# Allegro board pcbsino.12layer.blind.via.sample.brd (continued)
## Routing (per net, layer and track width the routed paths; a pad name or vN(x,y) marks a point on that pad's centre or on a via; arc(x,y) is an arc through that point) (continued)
VDD_GPU: length 26.6
  TOP w0.114: L6.2 18.88,64.43 ; TP13.1 16.45,63.67 16.65,63.87 v7(16.76,63.87) ; 17.72,63.51 v7(17.59,63.39)
  TOP w0.254: v8(33.47,31.97) U6.W11 v8(33.47,32.77) U6.W10 ; v8(33.47,31.97) U6.W10 ; v8(33.47,31.97) U6.V11 ; v8(33.47,31.97) U6.V10 ; U6.W10 v8(34.27,31.97) U6.V10 ; v8(33.47,31.17) U6.U11 v8(32.67,31.17) ; v8(33.47,31.17) U6.V11 ; v8(33.47,31.17) U6.V10 ; U6.V14 v8(31.07,31.97) U6.W13 ; U6.V11 v8(32.67,31.17) ; v8(32.67,31.17) U6.U12
  INT_L3 w0.254: 27.5,57.37 28.01,57.37 28.34,57.04 28.34,56.99 28.44,56.89 28.44,56.32 v2(28.34,56.22)
  INT_L3 w0.381: 27.5,57.37 27.07,56.93 25.98,56.93 25.52,57.39 24.78,57.39 18.79,63.39 v7(17.59,63.39)
  SIG_L10 w0.091: v3(30.5,47.1) 30.5,47.43 v5(30.55,47.49)
  BOTTOM w0.254: 33.16,31.57 33.16,31.49 v8(33.47,31.17) ; v8(31.07,31.97) 30.99,31.89 C247.1
  vias: v7(16.78,64.43) v7(17.37,64.43) v7(17.34,63.89)
VDD_IVA: length 25.7
  TOP w0.114: L8.2 17.95,51.85 TP18.1 v7(16.88,54.34)
  TOP w0.254: U6.V18 v8(27.07,31.17) ; v8(27.07,31.17) U6.V19 v8(26.27,31.17) U6.U19 v8(27.07,31.17) ; v8(27.07,31.17) U6.U18 ; U3.L11 v7(27.93,52.62)
  INT_L3 w0.381: v7(16.88,54.34) 16.96,54.42 23.31,54.42 24.2,53.53 27.02,53.53 v7(27.93,52.62)
  SIG_L10 w0.091: v5(26.31,46.06) 26,46.06 v3(25.72,46.34)
  BOTTOM w0.114: C39.1 17.05,52.83 C244.1 16.88,53.4 v7(16.88,54.34) ; v7(27.93,52.62) 28.63,51.92 C241.1
  vias: v4(25.26,46.93) v5(25.26,46.93) v7(16.5,54.75) v7(16.91,55.05) v7(17.42,54.99)
VDD_MPU: length 47.9
  TOP w0.254: U6.M18 v8(27.07,27.17) U6.N18 ; U6.M18 v8(27.87,26.37) ; U6.M18 v8(27.87,27.17) ; U6.M18 v8(27.07,26.37) ; U6.L18 v8(27.07,26.37) ; U6.L18 v8(27.07,25.57) ; U6.L18 v8(27.87,26.37) ; U6.L18 v8(27.87,25.57) ; v8(27.07,26.37) U6.L19 v8(27.07,25.57) ; v8(28.67,25.57) U6.L16 ; v8(28.67,25.57) U6.K17 v8(27.87,25.57) ; v8(28.67,25.57) U6.L17 ; U6.L16 v8(28.67,26.37) ; U6.L16 v8(29.47,26.37) ; 27.87,27.97 U6.P18 ; 27.87,27.97 U6.N18 ; 27.87,27.97 U6.N17 v8(27.87,27.17) ; 27.87,27.97 U6.P17 ; U6.P18 v8(27.07,27.97) ; U6.P18 27.83,28.73 27.83,28.79 27.47,29.15 ; 27.47,29.15 U6.R18 ; 27.47,29.15 27.37,29.06 27.37,28.81 27.12,28.56 27.12,28.19 27.07,28.13 v8(27.07,27.97) ; v8(27.87,26.37) U6.L17 ; v8(27.87,26.37) U6.M17 ; U6.L17 v8(27.87,25.57) ; U6.L17 v8(28.67,26.37) ; v8(27.07,25.57) U6.K18 v8(27.87,25.57) ; v8(29.47,26.37) U6.M16 v8(28.67,26.37) ; v8(29.47,26.37) U6.M15 ; v8(29.47,26.37) U6.L15 ; v8(27.07,27.97) U6.N18 ; v8(28.67,26.37) U6.M17 ; U6.N18 v8(27.87,27.17) ; v8(27.87,27.17) U6.M17
  TOP w0.381: L2.2 35.96,46.7 37.61,46.7 37.66,46.65 37.66,45.78 TP5.1 ; U3.B13 34.74,50.13 36.09,48.78 38.77,48.78 39.13,48.42 39.13,46.72 C19.1 ; v7(40.43,46.93) 39.75,46.93 ; 39.75,46.93 C19.1 ; 39.75,46.93 40.25,47.43 v7(40.43,47.43) ; C19.1 39.46,46.39 v7(40.43,46.39) ; C19.1 39.34,47.11 40.21,47.99 v7(40.4,47.99)
  SIG_L10 w0.381: v3(40.13,29.59) v4(40.13,29.12) 40.13,29.07 v5(39.82,28.77)
  BOTTOM w0.114: v8(27.87,25.57) 28.02,25.43 C256.1
  BOTTOM w0.381: C261.1 39.11,48.55 39.62,48.04 40.35,48.04 v7(40.4,47.99) ; 29.76,26.71 29.87,26.82 C257.1 ; L1.2 36.82,46.52 C20.1 39.36,46.52 40.23,47.4 40.39,47.4 v7(40.43,47.43)
VDD_RTC: length 6.3
  TOP w0.254: v8(29.47,35.17) U6.AB15
  TOP w0.381: TP24.1 39.32,56.6 38.53,56.6 38.06,57.07 C49.2 37.75,57.02 U3.A5
  BOTTOM w0.381: v8(29.47,35.17) 29.55,35.25 C63.1
  vias: v7(39.87,55.92)
VDD_SD: length 13.6
  TOP w0.254: U6.W8 v8(35.87,32.77) U6.Y8
  TOP w0.381: v7(33.55,56.58) 33.58,56.58 U3.C6 ; TP19.1 50.1,50.52 v2(50.12,50.52)
  INT_L3 w0.381: v7(50.74,51.04) 50.22,50.52 v2(50.12,50.52)
  SIG_L8 w0.381: v3(40.94,35.93) 41.77,35.93 42.26,36.41 42.26,38.01
  SIG_L10 w0.381: v5(41.17,35.29) 41.17,35.7 v3(40.94,35.93) ; v7(50.74,51.04) 49.9,51.88 v5(48.86,51.88) v3(48.86,52.62)
  BOTTOM w0.254: v8(35.87,32.77) 35.89,32.75 35.89,32.17
  BOTTOM w0.381: v7(33.55,56.58) 33.47,56.66 33.04,56.66 C40.2 ; R6.2 R3.2 48.15,52.48 Q2.2
VDDA_1V8_PHY_LDO3: length 1.5
  TOP w0.381: v7(24.38,49.07) 24.26,48.96 TP21.1 ; v7(27.92,51.82) 27.94,51.82 U3.K11
VDDA_1V8_PHY_LDO3_F: length 8.7
  TOP w0.254: U6.W12 v8(31.87,31.97) U6.V13 ; U6.AB12 v8(31.87,34.37) U6.AA13
  BOTTOM w0.114: C164.1 32.05,34.55 v8(31.87,34.37) ; C163.1 32.07,32.48 32.1,32.46 32.1,32.2 v8(31.87,31.97) ; L23.3 23.84,42.05 C297.1 23.97,41.92 C296.1 25.48,42.04 25.19,42.33 v7(25.19,42.69)
VDDA_1V8_PHY_LDO4: length 1.8
  TOP w0.381: TP22.1 21.89,49.14 v7(22.62,49.87) ; v7(27.97,51.03) 28.01,51.07 28.01,51.09 U3.K12
  BOTTOM w0.114: v7(22.62,49.87) 22.65,49.9
VDDA_1V8_PHY_LDO4_F: length 7.9
  TOP w0.254: U6.Y17 v8(27.87,33.57) U6.AA17 U6.AA16 ; v8(31.07,32.77) U6.W14
  BOTTOM w0.114: v8(19.92,42.03) C305.1 20.64,43.43 C306.1 20.9,44.44 L24.3
  BOTTOM w0.254: C303.1 27.7,33.74 v8(27.87,33.57) ; C304.1 31,32.7 v8(31.07,32.77)
VDDA_1V8_PLL: length 35.1
  TOP w0.254: U6.AE16 v8(28.67,36.77) U6.AD16
  TOP w0.381: TP25.1 43.48,60.03 43.48,57.7 43.1,57.32 v7(43.04,57.32) ; v7(34.33,56.62) U3.B5
  INT_L3 w0.381: v7(34.33,56.62) 35.31,57.59 42.56,57.59 42.84,57.32 v7(43.04,57.32)
  BOTTOM w0.381: L22.1 41,41.7 41.95,42.66 42.82,42.66 44.98,44.82 44.98,48.22 44.37,48.83 42.92,48.83 42.24,49.5 42.24,50.55 41.42,51.37 41.42,52.79 42.13,53.5 42.13,56.05 42.11,56.07 42.11,56.61 v5(42.16,56.66)
  vias: v4(29.79,45.1) v5(29.79,45.1)
VDDA_1V8_PLL_F: length 8.5
  TOP w0.254: v8(29.47,27.97) U6.N16 v8(28.67,27.97) U6.P16 v8(29.47,27.97) ; v8(29.47,27.97) U6.P15 ; U6.R14 30.72,29.17 v8(31.1,28.8) U6.P14 ; v8(27.87,29.57) U6.R17 ; U6.N12 v8(32.67,27.17) U6.N11
  INT_L3 w0.381: v8(31.1,28.8) 30.55,28.25 30.55,26.91 v2(30.67,26.78)
  BOTTOM w0.381: C301.1 32.52,27.32 v8(32.67,27.17)
  vias: v5(39.54,37.17) v5(39.58,37.65) v5(39.72,36.84) v5(39.95,37.73) v5(39.9,37.35) v5(40.02,37.07)
VDDS_DDR: length 159.8
  TOP w0.114: C82.2 3.09,41.03 2.73,41.39 v8(2.68,41.39) ; U9.R9 4.73,31.41 ; U9.N9 6.33,31.41 ; U10.N9 6.33,9.01
  TOP w0.254: U6.AB25 v8(22.27,35.17) U6.AB24 ; v8(14.7,15.78) 14.65,15.74 14.65,15.73 U10.C1 14.02,15.09 U10.D2 ; C124.2 6.02,18.52 6.02,19.89 U11.N9 ; U8.R9 4.73,42.61 4.13,42.01 C82.2 ; U9.R1 4.73,37.81 4.11,38.43 C98.1 ; v8(10.86,11.29) 10.86,10.87 U10.G7 ; U9.A8 v8(16.33,31.81) ; U8.B2 v8(15.53,48.61) ; U11.E9 v8(13.13,19.81) U11.D9 ; U10.E9 v8(13.13,8.61) ; U6.AH27 20.27,40.24 v8(20.08,40.42) ; v8(19.88,23.98) U6.J27 ; v8(24.67,34.37) U6.AB22 v8(24.67,35.17) ; v8(24.67,34.37) U6.AB21 v8(24.67,35.17) ; v8(24.67,34.37) U6.AA21 ; v8(24.67,34.37) U6.AA22 ; U6.H20 v8(25.47,23.17) U6.H21 24.67,23.17 ; U9.G7 v8(11.53,32.61) ; U11.A1 16.13,26.81 16.13,28.19 15.95,28.37 14.6,28.37 C127.2 14.51,27.22 v8(14.73,27.01) U11.C1 ; C89.2 5.88,39.74 5.88,38.25 6.33,37.81 U9.N1 ; C134.1 4.31,27.02 4.73,26.61 U11.R1 ; C81.2 6.03,49.25 U8.N1 ; C96.1 13.58,41.17 14.33,41.92 U8.C9 ; C96.1 13.53,41.11 U8.D9 ; C96.1 13.54,41.02 12.2,41.02 12.16,41.06 ; v8(24.67,35.17) U6.AC22 v8(23.87,35.97) ; U10.D9 v8(13.93,8.61) ; U9.D9 v8(13.93,31.01) ; U10.K8 v8(9.13,9.41) ; 6.33,31.41 v8(5.93,31.01) 6.02,30.92 6.02,29.41 ; U9.D2 13.53,37.01 v8(13.93,37.41) ; U10.R1 4.73,15.43 4.44,15.72 4.44,16.99 C133.1 ; U9.B2 15.13,37.01 v8(15.53,37.41) ; U9.C9 v8(14.73,31.01) ; v8(16.5,37.72) 16.42,37.81 U9.A1 ; C90.2 4.42,29.5 ; 4.42,29.5 4.42,29.41 ; 4.42,29.5 4.42,30.92 v8(4.33,31.01) 4.73,31.41 ; U8.R1 4.73,49.01 4.31,49.43 C93.1 ; U8.H9 v8(10.73,42.21) 10.76,42.18 C83.2 ; v8(25.47,26.37) U6.L21 v8(24.67,26.37) U6.M21 v8(25.47,26.37) ; v8(25.47,26.37) U6.M20 ; v8(25.47,26.37) U6.L20 ; U8.N9 6.33,42.61 5.96,42.24 C94.1 ; U10.N1 5.91,15.83 5.91,17 6.02,17.11 C121.2 ; v8(15.97,16.04) 15.97,15.67 15.97,15.44 U10.A1 ; U9.K8 v8(8.33,31.81) ; U11.F1 v8(12.33,27.01) ; v8(23.87,23.17) U6.H22 24.67,23.17 ; v8(23.87,23.17) U6.G22 ; v8(23.87,23.17) U6.G23 23.87,22.37 U6.G22 ; U11.G7 v8(10.74,21.42) ; U11.H2 v8(10.73,26.21) ; U8.A1 v8(16.33,49.41) ; U9.H9 v8(10.73,31.01) ; U11.R9 4.73,20.21 4.42,19.89 4.42,18.61 C128.2 ; U6.G22 24.67,23.17 ; v8(22.27,20.77) U6.E24 ; U8.K2 v8(8.33,48.61) ; U8.A8 v8(16.33,43.01) ; 6.33,9.01 v8(5.93,8.61) 6.1,8.44 C129.1 ; C125.2 6.02,28.39 6.02,26.92 U11.N1 ; v8(10.75,44.63) 10.77,44.61 10.77,44.6 11.13,44.25 U8.G7 ; v8(14.73,38.21) 14.33,37.81 U9.C1 ; U9.F1 11.93,37.81 v8(12.33,38.21) ; U6.T24 v8(22.27,30.37) U6.T25 ; v8(10.73,37.41) 10.33,37.01 U9.H2 ; U10.H2 v8(10.73,15.01) ; U6.AG20 26.23,38.41 26.29,38.41 v8(26.31,38.39) ; U10.R9 4.53,8.81 4.53,8.81 v8(4.33,8.61) 4.42,8.52 4.42,7.4 C122.2 ; U3.K13 28.34,50.08 27.5,49.24 25.3,49.24 23.36,47.3 ; v8(14.73,14.21) 14.91,14.38 U10.B2 ; U10.C9 v8(14.73,8.61) ; v8(19.87,32.77) U6.W27 ; U8.D2 v8(13.93,48.61) ; U11.A8 16.76,20.17 C137.1 16.46,18.2 14.14,18.2 v8(14.06,18.28) 14.06,19.94 U11.C9 ; U8.C1 v8(14.73,49.41) ; v8(28.67,32.77) U6.W16 ; U10.K2 v8(8.33,15.01) ; v8(21.6,36.9) U6.AD26 ; U11.K8 v8(8.33,20.61) ; v8(8.33,37.41) 8.73,37.01 U9.K2 ; C273.1 11.49,16.65 12.05,16.09 12.05,15.53 U10.F1 ; U8.H2 v8(10.73,48.61) ; U10.H9 v8(10.73,8.61) ; U8.K8 v8(8.33,43.01) ; U11.B2 v8(15.53,26.21) ; U10.A8 v8(16.33,9.41) ; v8(19.07,39.17) U6.AG28 ; U11.H9 v8(10.73,19.81) ; U8.E9 v8(13.13,42.21) ; U9.E9 v8(13.13,31.01) ; U8.F1 v8(12.33,49.41) ; U11.D2 v8(13.93,26.21) ; U11.K2 v8(8.33,26.21)
  TOP w0.381: C273.1 11.49,17.73 v8(11.52,17.77) ; C85.2 16.08,50.67 15.9,50.49 15.9,49.84 v8(16.33,49.41) ; C125.2 6.03,29.4 6.02,29.41 ; v8(12.33,49.41) 12.33,49.89 12.54,50.1 ; C84.2 14.37,50.84 14.37,49.86 ; C101.1 16.5,39.3 v8(16.5,37.72) ; C83.2 11.92,41.02 v8(12.06,41.16) 12.16,41.06 C96.1 ; C134.1 4.31,28.39 C90.2 3.55,29.5 C123.1 3.04,30.37 v8(2.48,30.92) ; v8(14.73,49.41) 14.73,49.5 14.37,49.86 ; 14.37,49.86 v8(13.93,49.41)
  INT_L3 w0.091: v2(22.62,46.37) 22.62,45.92 v3(22.63,45.91)
  BOTTOM w0.114: C280.1 26.34,38.42 v8(26.31,38.39) ; v5(23.56,22.77) 23.83,22.5 C272.1 ; C267.1 24.6,23.14 v5(24.25,22.8) ; C277.1 28.77,32.67 v8(28.67,32.77)
  BOTTOM w0.254: C126.2 14.51,27.22 v8(14.73,27.01) U11.C1 14.33,26.52 ; 14.33,37.75 14.33,37.81 v8(14.73,38.21) ; 14.33,37.75 14.5,37.75 ; 14.33,37.75 14.33,37.72 ; v8(14.73,31.01) U9.C9 14.33,31.5 ; C275.1 20.06,32.31 20.06,32.58 v8(19.87,32.77) ; C279.1 20.46,39.93 20.46,40.04 v8(20.08,40.42) ; 24.18,23.57 24.18,23.48 v8(23.87,23.17) ; 8.73,25.9 8.64,25.9 v8(8.33,26.21) 8.31,26.23 C135.1 ; 13.53,31.5 U9.D9 v8(13.93,31.01) ; v8(13.93,37.41) 13.62,37.1 13.53,37.1 ; v8(8.33,15.01) 8.64,14.69 8.73,14.69 ; C281.1 22.07,35.37 v8(22.27,35.17) ; 15.94,43.31 16.06,43.19 16.15,43.19 v8(16.33,43.01) ; 15.94,43.31 15.93,43.32 ; 15.94,43.31 C95.1 ; C282.1 19.55,38.93 19.31,38.93 v8(19.07,39.17) ; C119.2 14.43,16.11 14.65,15.88 14.65,15.86 14.7,15.81 v8(14.7,15.78) ; C270.1 22.39,21.47 22.17,21.25 22.17,20.88 v8(22.27,20.77) ; v8(19.88,23.98) 20.22,24.33 ; C67.2 2.61,36.55 v7(2.48,36.68) ; v8(15.53,37.41) 15.22,37.1 15.13,37.1 ; 23.87,22.37 24.18,22.68 24.18,22.77 ; v8(10.73,26.21) 10.42,25.9 10.33,25.9 ; v8(13.13,31.01) U9.E9 12.73,31.5 ; 10.67,19.75 v8(10.73,19.81) ; v8(13.13,42.21) U8.E9 12.73,42.7 ; v8(22.27,30.37) 22.07,30.57 C278.1 ; v8(16.5,37.72) 15.93,37.72
  BOTTOM w0.381: v8(2.51,19.14) 2.56,19.08 C103.2 ; v8(24.67,34.37) 24.24,34.8 C276.1 ; v8(19.88,23.98) 20.03,23.82 C268.1 ; v8(11.53,32.61) 11.53,32.61 11.07,33.06 C269.1 10.07,33.26 C73.2 ; C104.2 9.33,6.16 10.02,6.16 10.46,6.6 10.46,7.76 ; C283.1 21.94,34.84 v8(22.27,35.17) ; C66.2 2.91,41.61 v8(2.68,41.39) ; C111.1 11.49,17.73 v8(11.52,17.77) ; v8(10.86,11.29) 10.62,11.04 C110.2 ; C68.2 2.53,30.87 v8(2.48,30.92) ; v8(8.33,48.61) 8.28,48.66 C92.1
  vias: v1(22.24,47.61) v1(22.24,47.28) v1(22.27,46.88) v1(22.24,46.52) v1(22.65,47.59) v1(22.65,47.23) v1(22.65,46.88) v1(23.05,47.23) v1(23.03,46.88) v1(23.05,46.47) v1(23.08,47.56) v2(22.24,47.61) v2(22.24,47.28) v2(22.27,46.88) v2(22.24,46.52) v2(22.65,47.59) v2(22.65,47.23) v2(22.65,46.88) v2(23.05,47.23) v2(23.03,46.88) v2(23.05,46.47) v2(23.08,47.56) v3(21.78,46.85) v3(21.83,46.27) v3(22.05,45.72) v3(22.47,45.32) v3(22.87,44.9) v3(23.05,45.48) v3(23.93,22.33) v3(24.68,22.95) v7(8.45,54.93) v7(9.16,54.93) v7(9.77,54.93) v7(10.38,54.93) v8(10.46,7.2) v8(12.16,7.05)
CLOCKOUT1: length 6.4
  TOP w0.12: v8(24.67,21.57) U6.F21
  SIG_L10 w0.091: v4(25.22,16.4) 25.22,21.02 v8(24.67,21.57)
  GND_L11 w0.091: v4(25.22,16.4) 25.4,16.22 v5(25.59,16.22)
CLOCKOUT3: length 8.9
  TOP w0.114: TP33.1 20.58,12.63 v2(20.59,12.61)
  TOP w0.12: v2(23.05,19.16) 23.06,19.16 U6.C23
  INT_L3 w0.091: v2(23.05,19.16) 23.05,18.83 22.37,18.15 22.37,15.89 20.59,14.11 v2(20.59,12.61)
DDR1_A0: length 54.8
  TOP w0.12: U8.N3 6.33,47.41 v8(5.93,47.81) ; v8(5.93,36.61) 6.33,36.21 U9.N3 ; v8(25.47,36.77) U6.AD20
  INT_L3 w0.094: v8(5.93,36.61) 5.53,37.01 5.53,41.24 6.34,42.05 6.34,45.5 5.93,45.92 v8(5.93,47.81)
  SIG_L10 w0.091: v8(25.47,36.77) 25.87,37.18 25.87,37.76 26.13,38.02 26.46,38.02 26.81,38.37 26.81,39.87 26.72,39.96 26.5,39.96 26.41,40.06 26.41,40.19 26.5,40.28 26.72,40.28 26.81,40.38 26.81,40.51 26.72,40.6 26.5,40.6 26.41,40.7 26.41,40.83 26.5,40.92 26.72,40.92 26.81,41.02 26.81,41.15 26.72,41.24 26.5,41.24 26.41,41.34 26.41,41.47 26.5,41.56 26.72,41.56 26.81,41.66 26.81,41.79 26.72,41.88 26.5,41.88 26.41,41.98 26.41,42.11 26.5,42.2 26.72,42.2 26.81,42.3 26.81,42.53 26.33,43.02 26.2,43.02 26.04,42.85 25.91,42.85 25.81,42.95 25.81,43.08 25.97,43.24 25.97,43.37 25.88,43.47 25.75,43.47 25.58,43.31 25.46,43.31 25.36,43.4 25.36,43.53 25.52,43.7 25.52,43.83 25.28,44.07 25.15,44.07 24.52,43.44 24.39,43.44 24.29,43.53 24.29,43.66 24.92,44.3 24.92,44.42 24.83,44.52 24.7,44.52 24.06,43.89 23.93,43.89 23.84,43.99 23.84,44.12 24.47,44.75 24.47,44.88 24.37,44.97 24.24,44.97 23.61,44.34 23.48,44.34 23.38,44.44 23.38,44.57 24.02,45.2 24.02,45.33 21.58,47.77 16.22,47.77 15.79,48.2 9.76,48.2 9.67,48.11 9.67,47.59 9.16,47.08 6.04,47.08 5.93,47.19 v8(5.93,47.81)
  BOTTOM w0.114: 5.93,36.01 5.91,35.99 R73.2
  BOTTOM w0.12: 5.93,36.01 v8(5.93,36.61)
DDR1_A1: length 54.8
  TOP w0.114: U9.P7 5.53,33.01
  TOP w0.12: v8(26.27,35.97) U6.AC19 ; U8.P7 5.53,44.21 v8(5.13,43.81) ; 5.53,33.01 v8(5.13,32.61)
  SIG_L8 w0.091: v8(26.27,35.97) 26.27,36.04 25.96,36.35 22.89,36.35 22.67,36.56 22.67,41.57 19.8,44.44 11.83,44.44 11.14,45.12 9.99,45.12 9.84,44.97 9.67,44.97 9.58,45.06 9.58,45.57 9.49,45.66 9.35,45.66 9.26,45.57 9.26,44.68 9.17,44.59 9.03,44.59 8.94,44.68 8.94,45.57 8.85,45.66 8.71,45.66 8.62,45.57 8.62,44.68 8.53,44.59 8.39,44.59 8.3,44.68 8.3,45.57 8.21,45.66 8.07,45.66 7.98,45.57 7.98,44.68 7.89,44.59 7.75,44.59 7.66,44.68 7.66,45.57 7.57,45.66 7.43,45.66 7.34,45.57 7.34,44.68 7.25,44.59 7.11,44.59 7.02,44.68 7.02,45.57 6.93,45.66 6.79,45.66 6.7,45.57 6.7,44.68 6.61,44.59 6.47,44.59 6.38,44.68 6.38,45.57 6.29,45.66 6.15,45.66 6.06,45.57 6.06,44.68 5.97,44.59 5.83,44.59 5.74,44.68 5.74,45.03 5.65,45.12 5.35,45.12 5.17,44.95 5.17,43.86 v8(5.13,43.81)
  SIG_L10 w0.094: v8(5.13,32.61) 5.13,35.45 5.51,35.83 5.51,40.63 4.73,41.4 4.73,43.41 v8(5.13,43.81)
  BOTTOM w0.114: v8(5.13,32.61) 5.05,32.69 R74.2
DDR1_A2: length 54.7
  TOP w0.12: U8.P3 5.53,47.41 v8(5.13,47.81) ; v8(25.47,35.97) U6.AC20 ; U9.P3 5.53,36.21 v8(5.13,36.61)
  INT_L3 w0.094: v8(5.13,36.61) 4.73,37.01 4.73,41.07 5.55,41.9 5.55,42.85 5.55,42.85 5.55,43.97 5.55,43.97 5.55,45.35 5.13,45.78 v8(5.13,47.81)
  SIG_L5 w0.091: v8(5.13,47.81) 5.13,48.02 5.5,48.4 5.5,48.77 5.5,49.19 6.45,50.13 6.45,50.33 6.57,50.46 6.77,50.46 6.9,50.58 6.9,50.79 7.02,50.91 7.23,50.91 7.35,51.04 7.35,51.24 7.48,51.36 7.68,51.36 7.94,51.63 18.92,51.63 27.47,43.07 27.47,42.48 27.57,42.39 27.76,42.39 27.86,42.3 27.86,42.16 27.76,42.07 27.57,42.07 27.47,41.98 27.47,41.84 27.57,41.75 27.76,41.75 27.86,41.66 27.86,41.52 27.76,41.43 27.57,41.43 27.47,41.34 27.47,41.2 27.57,41.11 27.76,41.11 27.86,41.02 27.86,40.88 27.76,40.79 27.57,40.79 27.47,40.7 27.47,40.56 27.57,40.47 27.76,40.47 27.86,40.38 27.86,40.24 27.76,40.15 27.57,40.15 27.47,40.06 27.47,39.92 27.57,39.83 27.76,39.83 27.86,39.74 27.86,39.6 27.76,39.51 27.57,39.51 27.47,39.42 27.47,39.28 27.57,39.19 27.76,39.19 27.86,39.1 27.86,38.96 27.76,38.87 27.57,38.87 27.47,38.78 27.47,36.62 27.2,36.35 25.84,36.35 v8(25.47,35.97)
  BOTTOM w0.114: R75.2 5.12,36.01 5.13,36.01
  BOTTOM w0.12: 5.13,36.01 v8(5.13,36.61)
DDR1_A3: length 54.7
  TOP w0.12: U9.N2 6.33,37.01 v8(5.93,37.41) ; U8.N2 6.33,48.21 v8(5.93,48.61) ; v8(26.27,35.17) U6.AB19
  SIG_L5 w0.094: v8(5.93,48.61) 5.93,48.41 5.53,48.01 5.53,41.16 5.93,40.76 v8(5.93,37.41)
  SIG_L8 w0.091: v8(5.93,48.61) 5.99,48.67 5.99,49.17 6.08,49.26 6.89,49.26 6.98,49.36 6.98,49.49 6.89,49.58 6.08,49.58 5.99,49.68 5.99,50.64 6.08,50.73 6.94,50.73 7.03,50.83 7.03,50.96 6.94,51.05 6.08,51.05 5.99,51.15 5.99,51.45 6.29,51.75 19.14,51.75 19.73,51.17 19.73,46.98 26.69,40.02 26.69,35.59 v8(26.27,35.17)
  BOTTOM w0.12: R76.2 6.33,38.69 6.33,37.81 v8(5.93,37.41)
DDR1_A4: length 54.8
  TOP w0.12: U8.P8 5.53,43.41 v8(5.13,43.01) ; v8(25.5,38.4) U6.AF21 ; U9.P8 5.53,32.21 v8(5.13,31.81)
  SIG_L5 w0.091: v8(5.13,31.81) 4.72,32.22 4.72,33.01 5.53,33.82 5.53,40.5 4.69,41.34 4.69,42.33 5.13,42.77 v8(5.13,43.01)
  SIG_L10 w0.091: v8(25.5,38.4) 25.46,38.4 24.86,39 24.86,40.78 22.63,43.01 22.5,43.01 22.44,42.94 22.31,42.94 22.22,43.04 22.22,43.17 22.28,43.23 22.28,43.36 22.18,43.46 22.05,43.46 21.99,43.4 21.86,43.4 21.76,43.49 21.76,43.62 21.82,43.68 21.82,43.81 21.24,44.4 21.11,44.4 20.84,44.12 20.71,44.12 20.61,44.21 20.61,44.34 20.89,44.62 20.89,44.75 20.79,44.85 20.66,44.85 20.38,44.57 20.25,44.57 20.16,44.67 20.16,44.8 20.44,45.07 20.44,45.2 19.3,46.34 18.61,46.34 18.52,46.43 18.52,46.86 18.43,46.95 18.29,46.95 18.2,46.86 18.2,46.43 18.11,46.34 17.97,46.34 17.88,46.43 17.88,46.86 17.79,46.95 17.65,46.95 17.56,46.86 17.56,46.43 17.47,46.34 17.33,46.34 17.24,46.43 17.24,46.86 17.15,46.95 17.01,46.95 16.92,46.86 16.92,46.43 16.83,46.34 16.69,46.34 16.6,46.43 16.6,46.86 16.51,46.95 16.37,46.95 16.28,46.86 16.28,46.43 16.19,46.34 16.05,46.34 15.96,46.43 15.96,46.86 15.87,46.95 15.73,46.95 15.64,46.86 15.64,46.43 15.55,46.34 15.41,46.34 15.32,46.43 15.32,46.86 15.23,46.95 15.09,46.95 15,46.86 15,46.43 14.91,46.34 14.77,46.34 14.68,46.43 14.68,46.86 14.59,46.95 14.45,46.95 14.36,46.86 14.36,46.43 14.27,46.34 14.13,46.34 14.04,46.43 14.04,46.86 13.95,46.95 13.81,46.95 13.72,46.86 13.72,46.43 13.63,46.34 13.49,46.34 13.4,46.43 13.4,46.86 13.31,46.95 13.17,46.95 13.08,46.86 13.08,46.43 12.99,46.34 6.19,46.34 5.53,45.68 5.53,43.62 5.13,43.22 v8(5.13,43.01)
  BOTTOM w0.12: R77.2 4.73,30.68 4.73,31.41 v8(5.13,31.81)
DDR1_A5: length 54.7
  TOP w0.114: v8(23.87,39.99) 23.87,39.97 U6.AH22
  TOP w0.12: U9.P2 5.53,37.01 v8(5.13,37.41) ; U8.P2 5.53,48.21 v8(5.13,48.61)
  INT_L3 w0.091: v8(5.13,48.61) 5.05,48.69 5.05,50.26 5.14,50.35 5.49,50.35 5.58,50.44 5.58,50.58 5.49,50.67 5.14,50.67 5.05,50.76 5.05,50.9 5.14,50.99 5.49,50.99 5.58,51.08 5.58,51.22 5.49,51.31 5.14,51.31 5.05,51.4 5.05,51.75 5.35,52.06 5.71,52.06 5.83,51.93 6.03,51.93 6.15,52.06 6.35,52.06 6.47,51.93 6.67,51.93 6.79,52.06 6.99,52.06 7.11,51.93 7.31,51.93 7.43,52.06 7.63,52.06 7.75,51.93 7.95,51.93 8.07,52.06 8.27,52.06 8.39,51.93 8.59,51.93 8.71,52.06 8.91,52.06 9.03,51.93 9.23,51.93 9.35,52.06 9.55,52.06 9.67,51.93 9.87,51.93 10,52.06 10.19,52.06 10.32,51.93 10.51,51.93 10.64,52.06 10.83,52.06 10.96,51.93 11.15,51.93 11.28,52.06 11.47,52.06 11.6,51.93 11.79,51.93 11.92,52.06 12.11,52.06 12.24,51.93 12.43,51.93 12.56,52.06 12.75,52.06 12.88,51.93 13.07,51.93 13.2,52.06 13.39,52.06 13.52,51.93 13.71,51.93 13.84,52.06 14.03,52.06 14.16,51.93 14.35,51.93 14.48,52.06 14.67,52.06 14.8,51.93 14.99,51.93 15.12,52.06 15.31,52.06 15.44,51.93 15.63,51.93 15.76,52.06 15.95,52.06 16.08,51.93 16.27,51.93 16.4,52.06 16.59,52.06 16.72,51.93 16.91,51.93 17.04,52.06 17.52,52.06 20.46,49.11 20.46,45.05 20.74,44.77 20.74,44.64 20.6,44.51 20.6,44.38 20.7,44.28 20.83,44.28 20.97,44.42 21.09,44.42 21.19,44.32 21.19,44.19 21.05,44.05 21.05,43.92 21.15,43.83 21.28,43.83 21.42,43.96 21.55,43.96 21.64,43.87 21.64,43.74 21.51,43.6 21.51,43.47 21.6,43.37 21.73,43.37 21.87,43.51 22,43.51 22.1,43.41 22.1,43.29 21.96,43.15 21.96,43.02 22.06,42.92 22.19,42.92 22.32,43.06 22.45,43.06 22.55,42.96 22.55,42.83 22.41,42.7 22.41,42.57 22.51,42.47 22.64,42.47 22.78,42.61 22.91,42.61 23,42.51 23,42.38 22.86,42.24 22.86,42.11 22.96,42.02 23.09,42.02 23.23,42.15 23.36,42.15 23.45,42.06 23.45,41.93 23.32,41.79 23.32,41.66 23.41,41.56 23.54,41.56 23.68,41.7 23.81,41.7 23.91,41.6 23.91,41.47 23.77,41.34 23.77,41.21 23.87,41.11 24,41.11 24.13,41.25 24.26,41.25 24.63,40.88 24.63,40.17 24.45,39.99 v8(23.87,39.99)
  SIG_L5 w0.094: v8(5.13,48.61) 4.72,48.2 4.72,42.74 4.41,42.43 4.41,38.13 v8(5.13,37.41)
  BOTTOM w0.12: R78.2 5.53,38.71 5.53,37.81 v8(5.13,37.41)
DDR1_A6: length 54.8
  TOP w0.12: v8(23.07,39.17) U6.AG23 ; v8(4.33,31.81) 4.73,32.21 U9.R8 ; v8(4.33,43.01) 4.73,43.41 U8.R8
  INT_L3 w0.091: v8(4.33,43.01) 4.7,43.39 4.7,47.93 4.97,48.2 5.35,48.2 5.53,48.37 5.53,49.06 5.86,49.39 6.56,49.39 6.65,49.48 6.65,49.62 6.56,49.71 6,49.71 5.91,49.8 5.91,49.94 6,50.03 6.56,50.03 6.65,50.12 6.65,50.26 6.56,50.35 6,50.35 5.91,50.44 5.91,50.58 6,50.67 6.56,50.67 6.65,50.76 6.65,50.9 6.56,50.99 6,50.99 5.91,51.08 5.91,51.37 6.19,51.65 17.42,51.65 20.06,49.01 20.06,44.41 23.36,41.11 23.36,39.46 v8(23.07,39.17)
  SIG_L10 w0.091: v8(4.33,31.81) 4.72,32.2 4.72,40.78 4.33,41.17 v8(4.33,43.01)
  BOTTOM w0.12: R79.2 3.93,30.69 3.93,31.41 v8(4.33,31.81)
DDR1_A7: length 54.8
  TOP w0.114: U9.R2 v8(4.33,37.41) ; U8.R2 v8(4.33,48.61) ; v8(24.69,37.55) 25.02,37.22
  TOP w0.12: 25.02,37.22 U6.AE21
  SIG_L5 w0.094: v8(4.33,48.61) 3.93,48.21 3.93,37.91 4.33,37.51 v8(4.33,37.41)
  SIG_L8 w0.091: v8(4.33,48.61) 4.74,48.2 7.74,48.2 7.94,48.4 7.94,50.99 8.27,51.32 8.89,51.32 8.98,51.23 8.98,51.11 9.07,51.02 9.21,51.02 9.3,51.11 9.3,51.23 9.39,51.32 9.53,51.32 9.62,51.23 9.62,51.11 9.71,51.02 9.85,51.02 9.94,51.11 9.94,51.23 10.03,51.32 10.17,51.32 10.26,51.23 10.26,51.11 10.35,51.02 10.49,51.02 10.58,51.11 10.58,51.23 10.67,51.32 10.81,51.32 10.9,51.23 10.9,51.11 10.99,51.02 11.13,51.02 11.22,51.11 11.22,51.23 11.31,51.32 11.45,51.32 11.54,51.23 11.54,51.11 11.63,51.02 11.77,51.02 11.86,51.11 11.86,51.23 11.95,51.32 12.09,51.32 12.18,51.23 12.18,51.11 12.27,51.02 12.41,51.02 12.5,51.11 12.5,51.23 12.59,51.32 12.73,51.32 12.82,51.23 12.82,51.11 12.91,51.02 13.05,51.02 13.14,51.11 13.14,51.23 13.23,51.32 13.37,51.32 13.46,51.23 13.46,51.11 13.55,51.02 13.69,51.02 13.78,51.11 13.78,51.23 13.87,51.32 14.01,51.32 14.1,51.23 14.1,51.11 14.19,51.02 14.33,51.02 14.42,51.11 14.42,51.23 14.51,51.32 14.65,51.32 14.74,51.23 14.74,51.11 14.83,51.02 14.97,51.02 15.06,51.11 15.06,51.23 15.15,51.32 15.6,51.32 15.73,51.19 15.92,51.19 16.05,51.32 16.24,51.32 16.37,51.19 16.56,51.19 16.69,51.32 18.76,51.32 19.35,50.74 19.35,46.83 25.87,40.3 25.87,37.33 25.7,37.15 25.09,37.15 24.69,37.55 v8(24.69,37.55)
  BOTTOM w0.114: R80.2 4.46,37.54 v8(4.33,37.41)
DDR1_A8: length 54.7
  TOP w0.114: U9.T8 3.93,32.21 3.83,32.11
  TOP w0.12: v8(24.7,38.4) U6.AF22 ; v8(3.53,43.01) 3.93,43.41 U8.T8 ; 3.83,32.11 v8(3.53,31.81)
  SIG_L5 w0.091: v8(3.53,31.81) 3.95,32.23 3.95,37.52 3.53,37.94 v8(3.53,43.01)
  SIG_L10 w0.091: v8(3.53,43.01) 3.53,43.2 3.9,43.57 3.9,43.65 3.9,44.43 4,44.52 4.6,44.52 4.69,44.62 4.69,44.75 4.6,44.84 4,44.84 3.9,44.94 3.9,45.07 4,45.16 4.6,45.16 4.69,45.26 4.69,45.39 4.6,45.48 4,45.48 3.9,45.58 3.9,45.99 4.67,46.75 10.25,46.75 10.81,47.31 18.99,47.31 22.62,43.68 22.75,43.68 22.98,43.9 23.11,43.9 23.21,43.8 23.21,43.68 22.98,43.45 22.98,43.32 23.08,43.22 23.21,43.22 23.43,43.45 23.56,43.45 23.66,43.35 23.66,43.22 23.43,43 23.43,42.87 23.53,42.77 23.66,42.77 23.88,43 24.01,43 24.11,42.9 24.11,42.77 23.88,42.54 23.88,42.41 23.98,42.32 24.11,42.32 24.34,42.54 24.47,42.54 24.56,42.45 24.56,42.32 24.34,42.09 24.34,41.96 24.43,41.86 24.56,41.86 24.79,42.09 24.92,42.09 25.02,41.99 25.02,41.86 24.79,41.64 24.79,41.51 24.89,41.41 25.02,41.41 25.24,41.64 25.37,41.64 25.47,41.54 25.47,41.41 25.24,41.19 25.24,41.06 25.9,40.4 25.9,38.24 25.67,38.01 25.09,38.01 v8(24.7,38.4)
  BOTTOM w0.12: v8(3.53,31.81) 3.13,31.41 3.13,30.68 R81.2
DDR1_A9: length 54.5
  TOP w0.114: U6.AE22 24.27,37.23 v8(23.89,37.61) ; U8.R3 v8(4.33,47.81)
  TOP w0.12: v8(4.33,36.61) 4.73,36.21 U9.R3
  INT_L3 w0.094: v8(4.33,36.61) 3.93,37.01 3.93,47.43 4.31,47.81 v8(4.33,47.81)
  SIG_L8 w0.091: v8(4.33,47.81) 4.33,46.91 4.79,46.44 5.16,46.44 5.26,46.54 5.26,47.09 5.35,47.18 5.48,47.18 5.58,47.09 5.58,46.54 5.67,46.44 5.8,46.44 5.9,46.54 5.9,47.09 5.99,47.18 6.12,47.18 6.22,47.09 6.22,46.54 6.31,46.44 6.44,46.44 6.54,46.54 6.54,47.09 6.63,47.18 6.76,47.18 6.86,47.09 6.86,46.54 6.95,46.44 7.08,46.44 7.18,46.54 7.18,47.09 7.27,47.18 7.4,47.18 7.5,47.09 7.5,46.54 7.59,46.44 7.72,46.44 7.82,46.54 7.82,47.09 7.91,47.18 8.04,47.18 8.14,47.09 8.14,46.54 8.23,46.44 8.36,46.44 8.46,46.54 8.46,47.09 8.55,47.18 8.68,47.18 8.78,47.09 8.78,46.54 8.87,46.44 9,46.44 9.1,46.54 9.1,47.09 9.19,47.18 9.32,47.18 9.42,47.09 9.42,46.54 9.51,46.44 11.32,46.44 11.78,45.99 12.22,45.99 12.31,46.08 12.31,46.28 12.4,46.37 12.54,46.37 12.63,46.28 12.63,46.08 12.72,45.99 12.86,45.99 12.95,46.08 12.95,46.28 13.04,46.37 13.18,46.37 13.27,46.28 13.27,46.08 13.36,45.99 13.5,45.99 13.59,46.08 13.59,46.28 13.68,46.37 13.82,46.37 13.91,46.28 13.91,46.08 14,45.99 14.14,45.99 14.23,46.08 14.23,46.28 14.32,46.37 14.46,46.37 14.55,46.28 14.55,46.08 14.64,45.99 14.78,45.99 14.87,46.08 14.87,46.28 14.96,46.37 15.1,46.37 15.19,46.28 15.19,46.08 15.28,45.99 15.42,45.99 15.51,46.08 15.51,46.28 15.6,46.37 15.74,46.37 15.83,46.28 15.83,46.08 15.92,45.99 16.06,45.99 16.15,46.08 16.15,46.28 16.24,46.37 16.38,46.37 16.47,46.28 16.47,46.08 16.56,45.99 16.7,45.99 16.79,46.08 16.79,46.28 16.88,46.37 17.02,46.37 17.11,46.28 17.11,46.08 17.2,45.99 17.34,45.99 17.43,46.08 17.43,46.28 17.52,46.37 17.66,46.37 17.75,46.28 17.75,46.08 17.84,45.99 19.22,45.99 24.3,40.91 24.3,38.11 23.89,37.71 v8(23.89,37.61)
  BOTTOM w0.114: R82.2 4.28,35.97
  BOTTOM w0.12: 4.28,35.97 4.28,36.57 v8(4.33,36.61)
DDR1_A10: length 54.6
  TOP w0.12: U9.L7 v8(7.53,32.61) ; v8(24.67,36.77) U6.AD21 ; U8.L7 v8(7.53,43.81)
  SIG_L10 w0.094: v8(24.67,36.77) 24.3,37.14 24.3,38.9 24.38,38.98 24.38,40.17 23.84,40.71 23.84,40.84 23.94,40.95 23.94,41.08 23.85,41.18 23.72,41.18 23.61,41.07 23.48,41.07 23.38,41.17 23.38,41.3 23.49,41.41 23.49,41.54 23.39,41.64 23.26,41.64 23.15,41.53 23.02,41.53 22.92,41.62 22.92,41.76 23.03,41.86 23.03,42 22.94,42.09 22.8,42.09 22.7,41.98 22.56,41.98 22.47,42.08 22.47,42.21 22.58,42.32 22.58,42.45 22.48,42.55 22.35,42.55 22.24,42.44 22.11,42.44 21.94,42.61 21.74,42.61 21.59,42.46 21.59,42.09 21.5,42 21.36,42 21.27,42.09 21.27,43.61 21.17,43.7 21.04,43.7 20.95,43.61 20.95,42.09 20.85,42 20.72,42 20.62,42.09 20.62,42.46 20.53,42.56 20.31,42.56 20.16,42.71 20.16,43.68 20.07,43.78 19.89,43.78 19.75,43.64 19.75,42.65 19.66,42.56 19.44,42.56 19.35,42.65 19.35,43.86 19.25,43.95 18.93,43.95 18.84,44.05 18.84,44.18 18.93,44.27 19.76,44.27 19.85,44.37 19.85,44.5 19.76,44.6 18.93,44.6 18.84,44.69 18.84,44.83 18.93,44.92 19.76,44.92 19.85,45.01 19.85,45.15 19.76,45.24 19.44,45.24 19.35,45.34 19.35,45.82 19.25,45.91 19.21,45.91 19.2,45.92 18.67,45.92 18.58,45.82 18.58,45.65 18.48,45.56 18.35,45.56 18.25,45.65 18.25,45.82 18.16,45.92 18.03,45.92 17.93,45.82 17.93,45.65 17.84,45.56 17.7,45.56 17.61,45.65 17.61,45.82 17.51,45.92 17.38,45.92 17.29,45.82 17.29,45.65 17.19,45.56 17.06,45.56 16.96,45.65 16.96,45.82 16.87,45.92 16.73,45.92 16.64,45.82 16.64,45.65 16.55,45.56 16.41,45.56 16.32,45.65 16.32,45.82 16.22,45.92 16.09,45.92 16,45.82 16,45.65 15.9,45.56 15.77,45.56 15.67,45.65 15.67,45.82 15.46,46.04 7.99,46.04 7.53,45.57 v8(7.53,43.81) 7.53,41.93 7.91,41.55 7.91,35.79 7.58,35.46 7.58,32.66 v8(7.53,32.61)
  BOTTOM w0.114: R83.2 7.48,32.65 v8(7.53,32.61)
DDR1_A11: length 54.9
  TOP w0.114: U9.R7 4.73,33.01
  TOP w0.12: 4.73,33.01 v8(4.33,32.61) ; v8(23.87,36.77) U6.AD22 ; v8(4.33,43.81) 4.73,44.21 U8.R7
  SIG_L8 w0.091: v8(23.87,36.77) 23.46,37.19 23.46,41.24 19.24,45.45 18.41,45.45 18.32,45.36 18.32,44.81 18.23,44.72 18.09,44.72 18,44.81 18,45.36 17.91,45.45 17.77,45.45 17.68,45.36 17.68,44.81 17.59,44.72 17.45,44.72 17.36,44.81 17.36,45.36 17.27,45.45 17.13,45.45 17.04,45.36 17.04,44.81 16.95,44.72 16.81,44.72 16.72,44.81 16.72,45.36 16.63,45.45 16.49,45.45 16.4,45.36 16.4,44.81 16.31,44.72 16.17,44.72 16.08,44.81 16.08,45.36 15.99,45.45 15.85,45.45 15.76,45.36 15.76,44.81 15.67,44.72 15.53,44.72 15.44,44.81 15.44,45.36 15.35,45.45 15.21,45.45 15.12,45.36 15.12,44.81 15.03,44.72 14.89,44.72 14.8,44.81 14.8,45.36 14.71,45.45 14.57,45.45 14.48,45.36 14.48,44.81 14.39,44.72 14.25,44.72 14.16,44.81 14.16,45.36 14.06,45.45 13.93,45.45 13.84,45.36 13.84,44.81 13.74,44.72 13.61,44.72 13.52,44.81 13.52,45.36 13.42,45.45 13.29,45.45 13.2,45.36 13.2,44.81 13.1,44.72 12.97,44.72 12.88,44.81 12.88,45.36 12.78,45.45 12.65,45.45 12.56,45.36 12.56,44.81 12.46,44.72 12.33,44.72 12.24,44.81 12.24,45.36 12.14,45.45 11.6,45.45 11.07,45.99 10.55,45.99 10.46,45.9 10.46,45.57 10.37,45.48 10.23,45.48 10.14,45.57 10.14,45.9 10.05,45.99 4.79,45.99 4.33,45.52 v8(4.33,43.81)
  SIG_L10 w0.094: v8(4.33,32.61) 3.93,33.01 3.93,43.19 4.33,43.59 v8(4.33,43.81)
  BOTTOM w0.114: R84.2 4.23,32.7 v8(4.33,32.61)
DDR1_A12: length 54.8
  TOP w0.12: U9.N7 6.33,33.01 v8(5.93,32.61) ; v8(5.93,43.81) 6.33,44.21 U8.N7 ; v8(24.67,35.97) U6.AC21
  SIG_L8 w0.091: v8(5.93,43.81) 5.93,44.05 6.16,44.29 7.03,44.29 7.15,44.16 7.15,42.15 7.61,41.69 8.99,41.69 9.08,41.79 9.08,42.34 9.17,42.43 9.31,42.43 9.4,42.34 9.4,41.79 9.49,41.69 9.63,41.69 9.72,41.79 9.72,42.34 9.81,42.43 9.95,42.43 10.04,42.34 10.04,41.79 10.13,41.69 13.5,41.69 13.6,41.79 13.6,42.52 13.78,42.71 14.02,42.71 14.12,42.81 14.12,43.36 14.21,43.45 14.34,43.45 14.44,43.36 14.44,42.34 14.53,42.25 14.66,42.25 14.76,42.34 14.76,43.3 14.85,43.4 14.98,43.4 15.08,43.3 15.08,42.34 15.17,42.25 15.3,42.25 15.4,42.34 15.4,42.62 15.49,42.71 15.72,42.71 15.82,42.8 15.82,43.91 15.91,44.01 16.71,44.01 16.8,43.91 16.8,43.03 16.89,42.94 17.03,42.94 17.12,43.03 17.12,43.91 17.21,44.01 17.35,44.01 17.44,43.91 17.44,43.03 17.53,42.94 17.67,42.94 17.76,43.03 17.76,43.91 17.85,44.01 19.65,44.01 21.89,41.77 21.89,37.3 22.14,37.05 22.14,36.18 22.73,35.59 24.29,35.59 v8(24.67,35.97)
  SIG_L10 w0.094: v8(5.93,43.81) 5.81,43.69 5.81,43.5 5.53,43.22 5.53,41.34 6.31,40.56 6.31,36.08 5.93,35.71 v8(5.93,32.61)
  BOTTOM w0.114: R85.2 5.86,32.68 v8(5.93,32.61)
DDR1_A13: length 54.6
  TOP w0.114: U6.AF18 v2(27.11,38.33)
  TOP w0.12: U9.T3 3.93,36.21 v8(3.53,36.61) ; U8.T3 3.93,47.41 v8(3.53,47.81)
  INT_L3 w0.091: 27.07,38.37 v2(27.11,38.33)
  INT_L3 w0.094: 27.07,38.37 27.07,38.9 20.87,45.1 20.87,49.24 17.75,52.36 4.89,52.36 3.78,51.24 3.78,50.79 3.87,50.7 4.6,50.7 4.69,50.6 4.69,50.47 4.6,50.37 3.87,50.37 3.78,50.28 3.78,50.14 3.87,50.05 4.6,50.05 4.69,49.96 4.69,49.82 4.6,49.73 3.87,49.73 3.78,49.63 3.78,49.5 3.87,49.4 4.6,49.4 4.69,49.31 4.69,49.18 4.6,49.08 3.87,49.08 3.78,48.99 3.78,48.06 v8(3.53,47.81) 3.13,47.41 3.13,37.01 v8(3.53,36.61)
  BOTTOM w0.114: R86.2 3.46,35.95 3.53,36.01
  BOTTOM w0.12: 3.53,36.01 v8(3.53,36.61)
DDR1_A14: length 54.8
  TOP w0.114: U9.T7 3.93,33.01
  TOP w0.12: U8.T7 3.93,44.21 v8(3.53,43.81) ; v8(27.87,37.57) U6.AE17 ; 3.93,33.01 v8(3.53,32.61)
  SIG_L5 w0.091: v8(27.87,37.57) 28.29,37.99 28.29,42.69 18.91,52.06 6.8,52.06 6.18,51.44 6.18,51.27 6.05,51.13 5.87,51.13 5.73,50.99 5.73,50.81 5.59,50.68 5.42,50.68 4.83,50.09 4.83,49.94 4.68,49.79 4.53,49.79 4.38,49.64 4.38,49.49 4.23,49.34 4.08,49.34 3.57,48.83 3.57,48.45 3.09,47.97 3.09,44.24 v8(3.53,43.81)
  SIG_L10 w0.094: v8(3.53,43.81) 3.13,43.41 3.13,33.01 v8(3.53,32.61)
  BOTTOM w0.114: v8(3.53,32.61) 3.45,32.69 R87.2
DDR1_A15: length 54.8
  TOP w0.12: v8(6.73,43.81) 7.13,44.21 U8.M7 ; U9.M7 7.13,33.01 v8(6.73,32.61) ; v8(27.07,36.77) U6.AD18
  SIG_L5 w0.091: v8(6.73,43.81) 7.1,44.19 7.1,47.65 7.1,47.66 7.1,48.77 7.1,48.96 8.7,50.56 9.23,50.56 9.32,50.47 9.32,50.42 9.41,50.33 9.55,50.33 9.64,50.42 9.64,50.47 9.73,50.56 9.87,50.56 9.96,50.47 9.96,50.42 10.05,50.33 10.19,50.33 10.28,50.42 10.28,50.47 10.37,50.56 10.51,50.56 10.6,50.47 10.6,50.42 10.69,50.33 10.83,50.33 10.92,50.42 10.92,50.47 11.01,50.56 11.15,50.56 11.24,50.47 11.24,50.42 11.33,50.33 11.47,50.33 11.56,50.42 11.56,50.47 11.65,50.56 11.79,50.56 11.88,50.47 11.88,50.42 11.97,50.33 12.11,50.33 12.2,50.42 12.2,50.47 12.29,50.56 12.43,50.56 12.52,50.47 12.52,50.42 12.61,50.33 12.75,50.33 12.84,50.42 12.84,50.47 12.93,50.56 13.07,50.56 13.16,50.47 13.16,50.42 13.25,50.33 13.39,50.33 13.48,50.42 13.48,50.47 13.57,50.56 13.71,50.56 13.8,50.47 13.8,50.42 13.89,50.33 14.03,50.33 14.12,50.42 14.12,50.47 14.21,50.56 14.35,50.56 14.44,50.47 14.44,50.42 14.53,50.33 14.67,50.33 14.76,50.42 14.76,50.47 14.85,50.56 14.99,50.56 15.08,50.47 15.08,50.42 15.17,50.33 15.31,50.33 15.4,50.42 15.4,50.47 15.49,50.56 15.63,50.56 15.72,50.47 15.72,50.42 15.81,50.33 15.95,50.33 16.04,50.42 16.04,50.47 16.13,50.56 16.27,50.56 16.36,50.47 16.36,50.42 16.45,50.33 16.59,50.33 16.68,50.42 16.68,50.47 16.77,50.56 17.28,50.56 17.38,50.46 17.6,50.46 17.7,50.56 17.92,50.56 18.02,50.46 18.24,50.46 18.34,50.56 19.17,50.56 26.69,43.04 26.69,42.46 26.6,42.36 26.42,42.36 26.33,42.27 26.33,42.14 26.42,42.04 26.6,42.04 26.69,41.95 26.69,41.82 26.6,41.72 26.42,41.72 26.33,41.63 26.33,41.5 26.42,41.4 26.6,41.4 26.69,41.31 26.69,41.18 26.6,41.08 26.42,41.08 26.33,40.99 26.33,40.86 26.42,40.76 26.6,40.76 26.69,40.67 26.69,40.54 26.6,40.44 26.42,40.44 26.33,40.35 26.33,40.22 26.42,40.12 26.6,40.12 26.69,40.03 26.69,39.9 26.6,39.8 26.42,39.8 26.33,39.71 26.33,39.58 26.42,39.48 26.6,39.48 26.69,39.39 26.69,37.15 v8(27.07,36.77)
  SIG_L10 w0.094: v8(6.73,32.61) 6.73,35.71 7.11,36.08 7.11,40.6 6.33,41.38 6.33,43.41 v8(6.73,43.81)
  BOTTOM w0.114: v8(6.73,32.61) 6.67,32.67 R88.2
DDR1_BA0: length 54.7
  TOP w0.12: U8.M2 7.13,48.21 v8(6.73,48.61) ; v8(6.73,37.41) 7.13,37.01 U9.M2 ; v8(27.87,38.37) U6.AF17
  INT_L3 w0.091: v8(6.73,48.61) 7.15,48.18 7.15,46.34 7.92,45.58 7.92,40.96 6.62,39.66 6.62,37.52 v8(6.73,37.41)
  SIG_L10 w0.091: v8(6.73,48.61) 6.62,48.72 6.62,50.34 7.27,50.99 15.44,50.99 15.53,50.9 15.53,50.32 15.62,50.23 15.76,50.23 15.85,50.32 15.85,50.9 15.94,50.99 16.08,50.99 16.17,50.9 16.17,50.32 16.26,50.23 16.4,50.23 16.49,50.32 16.49,50.9 16.58,50.99 16.72,50.99 16.81,50.9 16.81,50.32 16.9,50.23 17.04,50.23 17.13,50.32 17.13,50.9 17.22,50.99 17.36,50.99 17.45,50.9 17.45,50.32 17.54,50.23 17.68,50.23 17.77,50.32 17.77,50.9 17.86,50.99 18,50.99 18.09,50.9 18.09,50.32 18.18,50.23 18.32,50.23 18.41,50.32 18.41,50.9 18.5,50.99 18.64,50.99 18.73,50.9 18.73,50.32 18.82,50.23 18.96,50.23 19.05,50.32 19.05,50.9 19.14,50.99 19.63,50.99 27.87,42.75 v8(27.87,38.37)
  BOTTOM w0.12: v8(6.73,37.41) 7.13,37.81 7.13,38.68 R89.2
DDR1_BA1: length 54.9
  TOP w0.12: v8(27.07,37.57) U6.AE18 ; v8(5.93,31.81) 6.33,32.21 U9.N8 ; U8.N8 6.33,43.41 v8(5.93,43.01)
  SIG_L5 w0.091: v8(5.93,31.81) 6.35,32.23 6.35,41 5.93,41.42 v8(5.93,43.01) 6.35,43.43 6.35,48.77 7.86,50.27 7.86,50.4 7.76,50.5 7.76,50.63 7.85,50.72 7.98,50.72 8.08,50.63 8.21,50.63 8.7,51.12 9.04,51.12 9.13,51.03 9.13,51.01 9.22,50.91 9.36,50.91 9.45,51.01 9.45,51.03 9.54,51.12 9.68,51.12 9.77,51.03 9.77,51.01 9.86,50.91 10,50.91 10.09,51.01 10.09,51.03 10.18,51.12 10.32,51.12 10.41,51.03 10.41,51.01 10.5,50.91 10.64,50.91 10.73,51.01 10.73,51.03 10.82,51.12 10.96,51.12 11.05,51.03 11.05,51.01 11.14,50.91 11.28,50.91 11.37,51.01 11.37,51.03 11.46,51.12 11.6,51.12 11.69,51.03 11.69,51.01 11.78,50.91 11.92,50.91 12.01,51.01 12.01,51.03 12.1,51.12 12.24,51.12 12.33,51.03 12.33,51.01 12.42,50.91 12.56,50.91 12.65,51.01 12.65,51.03 12.74,51.12 12.88,51.12 12.97,51.03 12.97,51.01 13.06,50.91 13.2,50.91 13.29,51.01 13.29,51.03 13.38,51.12 13.52,51.12 13.61,51.03 13.61,51.01 13.7,50.91 13.84,50.91 13.93,51.01 13.93,51.03 14.02,51.12 14.16,51.12 14.25,51.03 14.25,51.01 14.34,50.91 14.48,50.91 14.57,51.01 14.57,51.03 14.66,51.12 14.8,51.12 14.89,51.03 14.89,51.01 14.98,50.91 15.12,50.91 15.21,51.01 15.21,51.03 15.3,51.12 15.44,51.12 15.53,51.03 15.53,51.01 15.62,50.91 15.76,50.91 15.85,51.01 15.85,51.03 15.94,51.12 16.08,51.12 16.17,51.03 16.17,51.01 16.26,50.91 16.4,50.91 16.49,51.01 16.49,51.03 16.58,51.12 16.72,51.12 16.81,51.03 16.81,51.01 16.9,50.91 17.04,50.91 17.13,51.01 17.13,51.03 17.22,51.12 17.36,51.12 17.45,51.03 17.45,51.01 17.54,50.91 17.68,50.91 17.77,51.01 17.77,51.03 17.86,51.12 18,51.12 18.09,51.03 18.09,51.01 18.18,50.91 18.32,50.91 18.41,51.01 18.41,51.03 18.5,51.12 19.04,51.12 27.07,43.09 v8(27.07,37.57)
  BOTTOM w0.12: R90.2 5.53,30.69 5.53,31.41 v8(5.93,31.81)
DDR1_BA2: length 54.8
  TOP w0.12: U9.M3 7.13,36.21 v8(6.73,36.61) ; U8.M3 7.13,47.41 v8(6.73,47.81) ; v8(27.07,35.17) U6.AB18
  INT_L3 w0.094: v8(6.73,47.81) 6.73,46.03 7.13,45.63 7.13,43.29 7.26,43.17 7.26,40.91 6.33,39.98 6.33,37.01 v8(6.73,36.61)
  SIG_L10 w0.091: v8(6.73,47.81) 7.13,48.21 7.13,49.24 7.79,49.9 8.11,49.9 8.2,49.99 8.2,50.19 8.29,50.28 8.43,50.28 8.52,50.19 8.52,49.99 8.61,49.9 8.75,49.9 8.84,49.99 8.84,50.26 8.93,50.36 9.07,50.36 9.16,50.26 9.16,49.99 9.25,49.9 9.39,49.9 9.48,49.99 9.48,50.26 9.57,50.36 9.71,50.36 9.8,50.26 9.8,49.99 9.89,49.9 10.03,49.9 10.12,49.99 10.12,50.26 10.21,50.36 10.35,50.36 10.44,50.26 10.44,49.99 10.53,49.9 10.67,49.9 10.76,49.99 10.76,50.26 10.85,50.36 10.99,50.36 11.08,50.26 11.08,49.99 11.17,49.9 11.31,49.9 11.4,49.99 11.4,50.26 11.49,50.36 11.63,50.36 11.72,50.26 11.72,49.99 11.81,49.9 11.95,49.9 12.04,49.99 12.04,50.26 12.13,50.36 12.27,50.36 12.36,50.26 12.36,49.99 12.45,49.9 12.59,49.9 12.68,49.99 12.68,50.26 12.77,50.36 12.91,50.36 13,50.26 13,49.99 13.09,49.9 13.23,49.9 13.32,49.99 13.32,50.26 13.41,50.36 13.55,50.36 13.64,50.26 13.64,49.99 13.73,49.9 13.87,49.9 13.96,49.99 13.96,50.26 14.05,50.36 14.19,50.36 14.28,50.26 14.28,49.99 14.37,49.9 14.51,49.9 14.6,49.99 14.6,50.26 14.69,50.36 14.83,50.36 14.92,50.26 14.92,49.99 15.01,49.9 20.29,49.9 27.49,42.69 27.49,35.6 v8(27.07,35.17)
  BOTTOM w0.114: 6.73,36.01 6.72,36.01 R91.2
  BOTTOM w0.12: 6.73,36.01 v8(6.73,36.61)
DDR1_CASN: length 54.8
  TOP w0.12: v8(8.33,36.61) 8.73,36.21 U9.K3 ; U8.K3 v8(8.33,47.81) ; v8(27.07,35.97) U6.AC18
  INT_L3 w0.094: v8(8.33,47.81) 8.33,46.87 9.54,45.66 9.54,41.29 7.91,39.65 7.91,37.03 v8(8.33,36.61)
  SIG_L10 w0.091: v8(27.07,35.97) 26.66,36.38 26.66,37.78 27.24,38.36 27.24,42.51 21.6,48.15 21.51,48.15 20.79,48.15 20.69,48.24 20.69,48.87 20.6,48.96 20.47,48.96 20.37,48.87 20.37,48.24 20.28,48.15 20.15,48.15 20.05,48.24 20.05,49.35 19.96,49.44 19.83,49.44 19.73,49.35 19.73,48.24 19.64,48.15 19.51,48.15 19.41,48.24 19.41,49.38 19.32,49.47 19.19,49.47 19.09,49.38 19.09,48.24 19,48.15 18.77,48.15 18.68,48.24 18.68,48.79 18.33,49.14 17.7,49.14 17.36,48.79 17.36,48.14 17.27,48.04 17.13,48.04 17.04,48.14 17.04,48.79 16.95,48.88 16.81,48.88 16.72,48.79 16.72,48.14 16.63,48.04 16.49,48.04 16.4,48.14 16.4,48.79 16.31,48.88 15.94,48.88 15.82,49.01 10.11,49.01 10.02,48.92 10.02,48.67 9.93,48.58 9.79,48.58 9.7,48.67 9.7,48.92 9.61,49.01 8.82,49.01 8.73,48.92 8.73,48.12 8.42,47.81 v8(8.33,47.81)
  BOTTOM w0.114: R71.2 8.37,35.97 8.33,36.01
  BOTTOM w0.12: 8.33,36.01 v8(8.33,36.61)
DDR1_CKE: length 54.5
  TOP w0.12: U9.K9 v8(8.33,31.01) ; U8.K9 v8(8.33,42.21) ; v8(23.87,39.17) U6.AG22
  SIG_L10 w0.094: v8(23.87,39.17) 22.93,40.11 22.93,40.91 22.22,41.62 17.19,41.62 16.88,41.92 16.88,42.27 16.98,42.37 18.36,42.37 18.46,42.46 18.46,42.59 18.36,42.69 16.98,42.69 16.88,42.78 16.88,42.92 16.98,43.01 18.36,43.01 18.46,43.1 18.46,43.24 18.36,43.33 16.98,43.33 16.88,43.43 16.88,43.56 16.98,43.66 18.36,43.66 18.46,43.75 18.46,43.88 18.36,43.98 16.98,43.98 16.88,44.07 16.88,44.21 16.98,44.3 18.36,44.3 18.46,44.4 18.46,44.53 18.36,44.62 16.98,44.62 16.88,44.72 16.88,44.85 16.98,44.95 18.36,44.95 18.46,45.04 18.46,45.17 18.36,45.27 15.34,45.27 14.85,45.76 8.37,45.76 7.93,45.31 7.93,42.58 8.3,42.21 v8(8.33,42.21) 8.71,41.83 8.71,35.65 7.93,34.87 7.93,31.41 v8(8.33,31.01)
  BOTTOM w0.114: R98.1 8.7,30.23 8.05,30.23 R68.2 7.97,30.65 v8(8.33,31.01)
DDR1_CLK_N: length 54.7
  TOP w0.114: U6.AH24 22.27,39.97 v8(22.27,40.02)
  TOP w0.12: U8.K7 v8(8.33,43.81) ; U9.K7 v8(8.33,32.61)
  SIG_L10 w0.094: v8(22.27,40.02) 22.13,40.15 22.13,40.58 21.89,40.82 21.27,40.82 20.13,39.69 19.85,39.69 19.04,40.5 17.92,40.5 17.63,40.21 17.63,39.29 17.53,39.2 17.21,39.2 17.11,39.29 17.11,40.87 16.87,41.11 16.34,41.11 16.1,40.87 16.1,39.24 16.01,39.15 15.72,39.15 15.64,39.23 15.64,40.91 15.41,41.14 14.96,41.14 14.73,40.91 14.73,39.31 14.65,39.23 14.44,39.23 14.36,39.31 14.36,40.45 14.13,40.68 13.73,40.68 13.5,40.45 13.5,39.31 13.36,39.17 12.96,39.17 12.87,39.27 12.87,40.75 13.53,41.42 13.9,41.42 14.42,41.93 14.42,42.27 14.02,42.67 14.02,42.8 14.18,42.96 14.3,42.96 14.71,42.54 15.39,42.54 15.88,43.04 15.88,43.71 14.44,45.15 13.54,45.15 13.3,44.91 13.3,44.63 13.21,44.53 13.02,44.53 12.93,44.63 12.93,44.91 12.69,45.15 12.3,45.15 12.06,44.91 12.06,44.63 11.96,44.53 11.78,44.53 11.68,44.63 11.68,45.03 11.44,45.27 8.91,45.27 8.56,44.92 8.56,44.09 8.33,43.86 v8(8.33,43.81) 8.47,43.81 8.71,43.57 8.71,43.12 9.57,42.26 9.57,34.25 8.6,33.29 8.6,32.88 v8(8.33,32.61)
  BOTTOM w0.102: R94.2 8.35,32.63 v8(8.33,32.61)
DDR1_CLK_P: length 54.7
  TOP w0.12: U8.J7 v8(9.13,43.81) ; U9.J7 v8(9.13,32.61) ; v8(22.27,39.17) U6.AG24
  SIG_L10 w0.094: v8(9.13,32.61) 9.05,32.61 8.85,32.81 8.85,33.18 9.81,34.15 9.81,42.36 8.96,43.22 8.96,43.64 v8(9.13,43.81) 9.1,43.81 8.81,44.11 8.81,44.82 9.01,45.02 11.34,45.02 11.43,44.93 11.43,44.52 11.67,44.29 12.07,44.29 12.3,44.52 12.3,44.81 12.4,44.9 12.59,44.9 12.68,44.81 12.68,44.52 12.92,44.29 13.31,44.29 13.55,44.52 13.55,44.81 13.64,44.9 14.34,44.9 15.64,43.61 15.64,43.14 15.29,42.79 14.81,42.79 14.4,43.21 14.08,43.21 13.77,42.9 13.77,42.57 14.17,42.17 14.17,42.03 13.8,41.66 13.43,41.66 12.62,40.86 12.62,39.16 12.86,38.93 13.47,38.93 13.75,39.21 13.75,40.35 13.83,40.43 14.03,40.43 14.11,40.35 14.11,39.21 14.34,38.98 14.75,38.98 14.98,39.21 14.98,40.81 15.06,40.89 15.31,40.89 15.39,40.81 15.39,39.13 15.62,38.9 16.11,38.9 16.35,39.14 16.35,40.77 16.44,40.86 16.77,40.86 16.86,40.77 16.86,39.19 17.1,38.95 17.63,38.95 17.87,39.19 17.87,40.11 18.02,40.25 18.94,40.25 19.75,39.44 20.24,39.44 21.37,40.58 21.79,40.58 21.89,40.48 21.89,39.79 22.27,39.41 v8(22.27,39.17)
  BOTTOM w0.102: v8(9.13,32.61) 9.14,32.62 R93.2
DDR1_CSN0: length 54.5
  TOP w0.114: U6.AH23 23.35,39.57 22.88,40.04 22.86,40.04 v2(22.85,40.06)
  TOP w0.12: v8(7.53,37.41) 7.93,37.01 U9.L2 ; U8.L2 v8(7.53,48.61)
  INT_L3 w0.091: v2(22.85,40.06) 22.85,41.11 19.7,44.26 19.7,48.88 17.31,51.27 16.58,51.27 16.49,51.18 16.49,50.75 16.4,50.66 16.26,50.66 16.17,50.75 16.17,51.18 16.08,51.27 15.94,51.27 15.85,51.18 15.85,50.75 15.76,50.66 15.62,50.66 15.53,50.75 15.53,51.18 15.44,51.27 15.3,51.27 15.21,51.18 15.21,50.75 15.12,50.66 14.98,50.66 14.89,50.75 14.89,51.18 14.8,51.27 14.66,51.27 14.57,51.18 14.57,50.75 14.48,50.66 14.34,50.66 14.25,50.75 14.25,51.18 14.16,51.27 14.02,51.27 13.93,51.18 13.93,50.75 13.84,50.66 13.7,50.66 13.61,50.75 13.61,51.18 13.52,51.27 13.38,51.27 13.29,51.18 13.29,50.75 13.2,50.66 13.06,50.66 12.97,50.75 12.97,51.18 12.88,51.27 12.74,51.27 12.65,51.18 12.65,50.75 12.56,50.66 12.42,50.66 12.33,50.75 12.33,51.18 12.24,51.27 12.1,51.27 12.01,51.18 12.01,50.75 11.92,50.66 11.78,50.66 11.69,50.75 11.69,51.18 11.6,51.27 11.46,51.27 11.37,51.18 11.37,50.75 11.28,50.66 11.14,50.66 11.05,50.75 11.05,51.18 10.96,51.27 10.82,51.27 10.73,51.18 10.73,50.75 10.64,50.66 10.5,50.66 10.41,50.75 10.41,51.18 10.32,51.27 10.18,51.27 10.09,51.18 10.09,50.75 10,50.66 9.86,50.66 9.77,50.75 9.77,51.18 9.68,51.27 9.54,51.27 9.45,51.18 9.45,50.75 9.36,50.66 9.22,50.66 9.13,50.75 9.13,51.18 9.04,51.27 8.9,51.27 8.81,51.18 8.81,50.75 8.72,50.66 8.58,50.66 8.49,50.75 8.49,51.18 8.4,51.27 7.92,51.27 7.53,50.88 v8(7.53,48.61)
  SIG_L5 w0.094: v8(7.53,48.61) 7.91,48.23 7.91,41.79 7.01,40.89 7.01,37.92 v8(7.53,37.41)
  BOTTOM w0.12: R69.2 7.93,38.72 7.93,37.81 v8(7.53,37.41)
DDR1_D0: length 20.9
  TOP w0.12: U8.H8 v8(10.73,43.01) ; v8(22.27,38.39) 21.87,37.99 U6.AF25
  SIG_L5 w0.091: v8(10.73,43.01) 10.28,42.56 10.28,41.85 11.98,40.15 12.6,40.15 12.69,40.05 12.69,39.8 12.78,39.71 12.96,39.71 13.05,39.8 13.05,40.05 13.15,40.15 13.33,40.15 13.42,40.05 13.42,39.8 13.51,39.71 13.69,39.71 13.79,39.8 13.79,40.05 13.88,40.15 14.06,40.15 14.15,40.05 14.15,39.8 14.24,39.71 14.43,39.71 14.52,39.8 14.52,40.05 14.61,40.15 14.79,40.15 14.88,40.05 14.88,39.8 14.97,39.71 15.16,39.71 15.25,39.8 15.25,40.05 15.34,40.15 15.52,40.15 15.61,40.05 15.61,39.8 15.71,39.71 15.89,39.71 15.98,39.8 15.98,40.05 16.07,40.15 16.26,40.15 16.35,40.05 16.35,39.8 16.44,39.71 16.62,39.71 16.71,39.8 16.71,40.05 16.8,40.15 16.99,40.15 17.08,40.05 17.08,39.8 17.17,39.71 17.35,39.71 17.44,39.8 17.44,40.05 17.54,40.15 18.66,40.15 20.92,37.88 21.76,37.88 v8(22.27,38.39)
DDR1_D1: length 20.9
  TOP w0.114: U8.F7 11.93,44.21 v8(11.53,43.81)
  TOP w0.12: v8(21.49,38.34) 21.12,37.97 U6.AF26
  SIG_L5 w0.091: v8(11.53,43.81) 11.53,43.78 11.12,43.37 11.12,41.42 11.88,40.65 12.44,40.65 12.54,40.76 12.54,41.07 12.64,41.16 12.82,41.16 12.91,41.07 12.91,40.72 13,40.63 13.18,40.63 13.28,40.72 13.28,41.07 13.37,41.16 13.55,41.16 13.64,41.07 13.64,40.72 13.73,40.63 13.92,40.63 14.01,40.72 14.01,41.07 14.1,41.16 14.28,41.16 14.37,41.07 14.37,40.72 14.46,40.63 14.65,40.63 14.74,40.72 14.74,41.07 14.83,41.16 15.01,41.16 15.1,41.07 15.1,40.72 15.2,40.63 15.38,40.63 15.47,40.72 15.47,41.07 15.56,41.16 15.74,41.16 15.84,41.07 15.84,40.72 15.93,40.63 16.11,40.63 16.2,40.72 16.2,41.07 16.29,41.16 16.48,41.16 16.57,41.07 16.57,40.82 16.66,40.73 16.84,40.73 16.93,40.82 16.93,41.07 17.02,41.16 17.54,41.16 18.2,40.5 18.76,40.5 20.92,38.34 21.38,38.34 21.38,38.34 v8(21.49,38.34)
DDR1_D2: length 20.9
  TOP w0.114: v8(19.7,41.03) 20.11,41.03 20.65,40.49 20.65,39.19 U6.AG26 ; v8(12.33,43.01) 11.93,43.41 U8.F8
  SIG_L5 w0.091: v8(12.33,43.01) 12.34,43.02 13.05,43.73 13.44,43.73 13.56,43.61 13.56,42.7 13.65,42.61 13.84,42.61 13.93,42.7 13.93,43.61 14.02,43.7 14.2,43.7 14.29,43.61 14.29,42.67 14.38,42.58 14.57,42.58 14.66,42.67 14.66,43.61 14.75,43.7 14.93,43.7 15.02,43.61 15.02,42.75 15.12,42.66 15.3,42.66 15.39,42.75 15.39,43.61 15.48,43.7 18.01,43.7 18.1,43.61 18.1,41.78 18.45,41.43 18.63,41.43 18.73,41.52 18.73,42.11 18.82,42.2 19,42.2 19.09,42.11 19.09,41.52 19.18,41.43 19.61,41.43 19.7,41.34 v8(19.7,41.03)
DDR1_D3: length 20.9
  TOP w0.12: U6.AH26 20.97,39.67 20.97,40.83 20.77,41.03 v8(20.77,41.19) ; U8.H3 v8(10.73,47.81)
  SIG_L5 w0.091: v8(10.73,47.81) 10.73,46.27 12.39,44.62 12.59,44.62 12.68,44.52 12.68,44.35 12.77,44.26 12.95,44.26 13.05,44.35 13.05,44.52 13.14,44.62 13.32,44.62 13.41,44.52 13.41,44.35 13.5,44.26 13.69,44.26 13.78,44.35 13.78,44.52 13.87,44.62 14.05,44.62 14.14,44.52 14.14,44.35 14.23,44.26 14.42,44.26 14.51,44.35 14.51,44.52 14.6,44.62 14.78,44.62 14.87,44.52 14.87,44.35 14.97,44.26 15.15,44.26 15.24,44.35 15.24,44.52 15.33,44.62 15.51,44.62 15.61,44.52 15.61,44.35 15.7,44.26 15.88,44.26 15.97,44.35 15.97,44.52 16.06,44.62 16.25,44.62 16.34,44.52 16.34,44.35 16.43,44.26 16.61,44.26 16.7,44.35 16.7,44.52 16.8,44.62 16.98,44.62 17.07,44.52 17.07,44.35 17.16,44.26 17.34,44.26 17.44,44.35 17.44,44.52 17.53,44.62 17.71,44.62 17.8,44.52 17.8,44.35 17.89,44.26 18.08,44.26 18.17,44.35 18.17,44.52 18.26,44.62 18.86,44.62 20.82,42.66 20.82,41.24 v8(20.77,41.19)
DDR1_D4: length 20.9
  TOP w0.114: v8(13.13,47.81) 13.13,47.75 12.79,47.41 U8.E3
  TOP w0.12: U6.AF24 23.07,38.37 v8(23.08,38.37)
  SIG_L5 w0.091: v8(23.08,38.37) 23.13,38.42 23.13,38.58 22.69,39.02 22.69,39.53 23.11,39.94 23.11,42.56 18.86,46.8 18.18,46.8 18.09,46.89 18.09,47.09 18,47.18 17.81,47.18 17.72,47.09 17.72,46.89 17.63,46.8 17.45,46.8 17.36,46.89 17.36,47.09 17.27,47.18 17.08,47.18 16.99,47.09 16.99,46.89 16.9,46.8 16.72,46.8 16.63,46.89 16.63,47.09 16.53,47.18 16.35,47.18 16.26,47.09 16.26,46.89 16.17,46.8 15.99,46.8 15.89,46.89 15.89,47.09 15.8,47.18 15.62,47.18 15.53,47.09 15.53,46.89 15.44,46.8 15.25,46.8 15.16,46.89 15.16,47.09 15.07,47.18 14.89,47.18 14.8,47.09 14.8,46.89 14.71,46.8 14.52,46.8 14.35,46.98 13.5,46.98 13.15,47.33 13.15,47.79 v8(13.13,47.81)
DDR1_D5: length 20.9
  TOP w0.12: v8(22.27,37.57) U6.AE24 ; U8.H7 v8(10.73,43.81)
  SIG_L5 w0.091: v8(10.73,43.81) 9.87,42.95 9.87,41.69 10.17,41.4 10.17,41.27 10.03,41.13 10.03,41 10.16,40.87 10.29,40.87 10.43,41.01 10.56,41.01 10.69,40.88 10.69,40.75 10.55,40.61 10.55,40.48 10.68,40.35 10.81,40.35 10.95,40.49 11.08,40.49 11.21,40.36 11.21,40.23 11.07,40.09 11.07,39.97 11.2,39.84 11.33,39.84 11.46,39.97 11.59,39.97 11.72,39.84 11.72,39.71 11.59,39.58 11.59,39.45 11.71,39.32 11.84,39.32 11.98,39.46 12.11,39.46 12.18,39.38 18.08,39.38 19.28,38.18 19.4,38.18 19.71,38.49 19.84,38.49 19.97,38.36 19.97,38.23 19.66,37.93 19.66,37.8 19.89,37.57 v8(22.27,37.57)
DDR1_D6: length 20.9
  TOP w0.12: U8.F2 v8(12.33,48.61) ; v8(23.9,38.4) U6.AF23
  SIG_L5 w0.091: v8(23.9,38.4) 24.03,38.4 24.38,38.75 24.38,40.25 24.17,40.45 24.17,40.61 24.32,40.76 24.32,40.98 24.17,41.13 24.17,41.34 24.32,41.5 24.32,41.71 24.17,41.86 24.17,42.07 24.32,42.23 24.32,42.56 18.86,48.02 16.83,48.02 15.84,49.01 12.64,49.01 12.33,48.7 v8(12.33,48.61)
DDR1_D7: length 20.9
  TOP w0.114: U8.G2 11.13,48.21 v8(11.53,48.61)
  TOP w0.12: v8(23.07,37.57) U6.AE23
  SIG_L5 w0.091: v8(11.53,48.61) 11.94,48.2 15.94,48.2 16.53,47.61 18.66,47.61 23.44,42.84 23.44,39.71 23.49,39.66 23.49,38 v8(23.07,37.57)
DDR1_D8: length 19.7
  TOP w0.114: v2(16.62,48.79) 16.51,48.79 U8.A2 ; U6.AC23 v2(23.77,35.27)
  INT_L3 w0.091: v2(16.62,48.79) 16.74,48.79 18.46,47.08 18.46,42.74 19.04,42.15 19.04,41.67 18.96,41.59 18.77,41.59 18.69,41.51 18.69,41.39 18.77,41.31 19.13,41.31 19.21,41.23 19.21,40.74 19.98,39.97 20.39,39.97 20.5,39.86 20.5,39.75 20.41,39.65 20.41,39.54 20.49,39.46 20.6,39.46 20.69,39.55 20.81,39.55 21.12,39.24 21.12,39.03 21.34,38.81 21.55,38.81 21.86,38.5 21.86,38.11 22.03,37.95 22.42,37.95 22.64,37.73 22.64,36.59 22.89,36.35 23.23,36.35 23.45,36.13 23.45,35.59 v2(23.77,35.27)
